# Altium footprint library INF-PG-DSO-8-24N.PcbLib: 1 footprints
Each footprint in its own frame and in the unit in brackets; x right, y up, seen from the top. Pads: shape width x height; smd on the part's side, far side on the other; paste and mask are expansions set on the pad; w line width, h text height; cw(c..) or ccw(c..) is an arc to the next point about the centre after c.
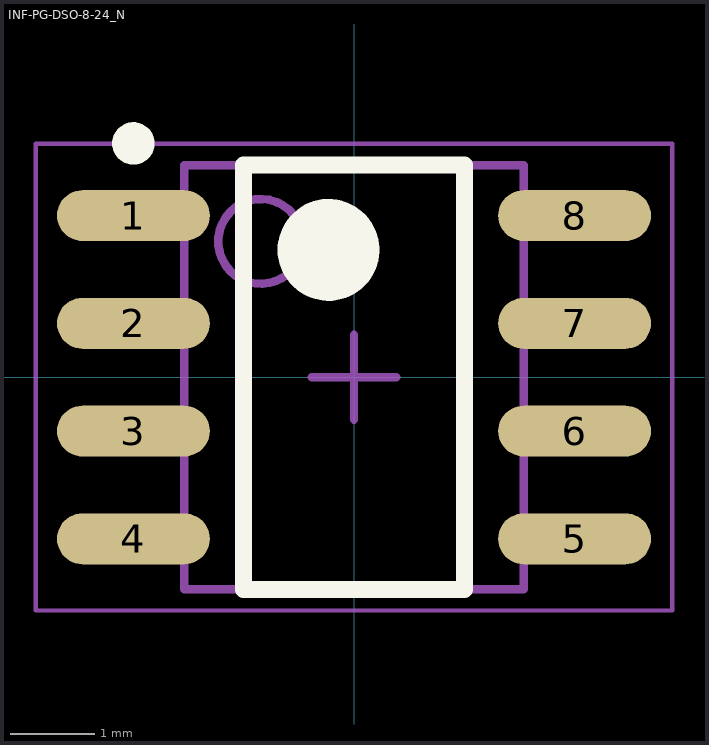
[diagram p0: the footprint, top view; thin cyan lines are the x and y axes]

## INF-PG-DSO-8-24_N [mm] "SOP, 8-Leads, Body 4.9x3.9mm, Pitch 1.27mm, IPC Medium Density"
height 1.75
pads (8):
  oval 1.8x0.6 smd: 1(-2.6,1.905) 2(-2.6,0.635) 3(-2.6,-0.635) 4(-2.6,-1.905) 5(2.6,-1.905) 6(2.6,-0.635) 7(2.6,0.635) 8(2.6,1.905)
Top Overlay:
  circle w0.25: c-2.6,2.755 r0.125
  circle w0.6: c-0.3,1.5 r0.3
  lines w0.2: -1.3,-2.5 -1.3,2.5 1.3,2.5 1.3,-2.5 -1.3,-2.5
Mechanical 13:
  circle w0.1: c-1.1,1.6 r0.5
  lines w0.1: -2,-2.5 -2,2.5 2,2.5 2,-2.5 -2,-2.5
Mechanical 15:
  lines w0.05: -3.75,-2.75 -3.75,2.75 3.75,2.75 3.75,-2.75 -3.75,-2.75
  lines w0.1: -0.5,0 0.5,0 ; 0,-0.5 0,0.5
3D body: height 1.75, standoff 0.1, extent -2,-2.5 2,2.5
